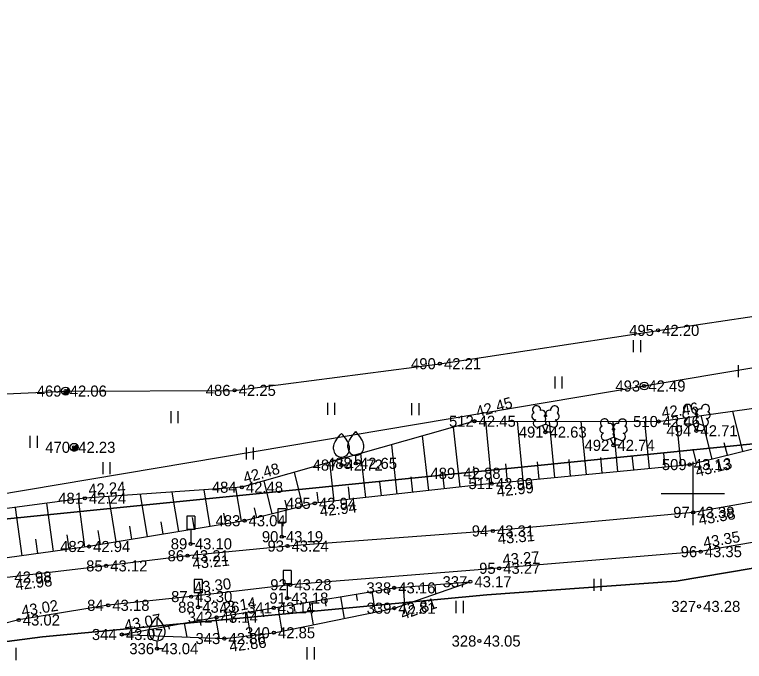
# Model space of a CAD drawing. Extents: x 505800 to 507326, y 6540058 to 6542128.
# Drawn here: x 506157.21 to 506203.25, y 6540239.39 to 6540280.22 of the extents above; entities that cross this region are included whole.
import ezdxf

# ---------------------------------------------------------------- set-up
doc = ezdxf.new("R2010")
doc.units = 0
for name, color, linetype in [('HALJASTUS', 7, 'Continuous'), ('KORGUS-EH2000', 7, 'Continuous'), ('LIIKLUS', 7, 'Continuous'), ('MOOTKORG-EH2000', 7, 'Continuous'), ('MOOTMPUNKT', 7, 'Continuous'), ('MOOTNR', 7, 'Continuous'), ('MOOTPIIR', 7, 'Continuous'), ('MPOHULIIN', 7, 'Continuous'), ('PIIR', 7, 'Continuous'), ('POST', 7, 'Continuous'), ('PUU', 7, 'Continuous'), ('RELJEEF', 7, 'Continuous'), ('TEE', 7, 'Continuous'), ('VORK', 7, 'Continuous')]:
    doc.layers.add(name, color=color, linetype=linetype)

msp = doc.modelspace()

# ---------------------------------------------------------------- linework, layer by layer
at = {"layer": 'HALJASTUS'}
for p, q in [((506196.246, 6540259.68), (506196.246, 6540258.919)), ((506196.701, 6540259.68), (506196.701, 6540258.919)), ((506202.852, 6540258.098), (506202.852, 6540257.337)), ((506191.291, 6540257.377), (506191.291, 6540256.616)), ((506191.746, 6540257.377), (506191.746, 6540256.616)), ((506176.948, 6540255.714), (506176.948, 6540254.953)), ((506177.403, 6540255.714), (506177.403, 6540254.953)), ((506182.253, 6540255.694), (506182.253, 6540254.933)), ((506182.708, 6540255.694), (506182.708, 6540254.933)), ((506167.059, 6540255.194), (506167.059, 6540254.433)), ((506167.514, 6540255.194), (506167.514, 6540254.433)), ((506158.171, 6540253.631), (506158.171, 6540252.87)), ((506158.626, 6540253.631), (506158.626, 6540252.87)), ((506171.813, 6540252.89), (506171.813, 6540252.129)), ((506172.268, 6540252.89), (506172.268, 6540252.129)), ((506162.775, 6540251.979), (506162.775, 6540251.218)), ((506163.23, 6540251.979), (506163.23, 6540251.218)), ((506193.745, 6540244.608), (506193.745, 6540243.847)), ((506194.2, 6540244.608), (506194.2, 6540243.847)), ((506185.057, 6540243.206), (506185.057, 6540242.445)), ((506185.512, 6540243.206), (506185.512, 6540242.445)), ((506157.286, 6540240.242), (506157.286, 6540239.481)), ((506175.648, 6540240.282), (506175.648, 6540239.521)), ((506176.103, 6540240.282), (506176.103, 6540239.521))]:
    msp.add_line(p, q, dxfattribs=at)
at = {"layer": 'KORGUS-EH2000'}
for centre in [(506197.806, 6540260.288), (506184.044, 6540258.184), (506196.936, 6540256.778), (506160.43, 6540256.455), (506171.091, 6540256.503), (506186.229, 6540254.552), (506197.842, 6540254.535), (506190.701, 6540253.865), (506200.224, 6540253.951), (506160.969, 6540252.907), (506194.987, 6540253.033), (506177.835, 6540251.786), (506178.739, 6540251.895), (506199.797, 6540251.818), (506187.313, 6540250.618), (506171.546, 6540250.385), (506161.646, 6540249.691), (506176.15, 6540249.371), (506200.022, 6540248.8), (506171.713, 6540248.272), (506187.383, 6540247.629), (506174.072, 6540247.265), (506161.906, 6540246.646), (506168.324, 6540246.815), (506174.426, 6540246.673), (506168.123, 6540246.063), (506200.494, 6540246.321), (506162.988, 6540245.422), (506187.779, 6540245.271), (506174.602, 6540244.231), (506185.963, 6540244.422), (506181.159, 6540244.035), (506168.346, 6540243.484), (506174.406, 6540243.388), (506163.12, 6540242.933), (506168.79, 6540242.813), (506173.563, 6540242.769), (506181.171, 6540242.752), (506200.392, 6540242.862), (506157.471, 6540242.007), (506169.957, 6540242.178), (506163.976, 6540241.09), (506173.57, 6540241.202), (506170.445, 6540240.835), (506186.532, 6540240.678), (506166.201, 6540240.196)]:
    msp.add_circle(centre, 0.1, dxfattribs=at)
at = {"layer": 'LIIKLUS'}
for p, q in [((506173.822, 6540249.015), (506173.822, 6540248.165)), ((506174.322, 6540249.015), (506173.822, 6540249.015)), ((506174.322, 6540249.015), (506174.322, 6540248.165)), ((506168.074, 6540248.565), (506168.074, 6540247.715)), ((506168.574, 6540248.565), (506168.074, 6540248.565)), ((506168.574, 6540248.565), (506168.574, 6540247.715)), ((506174.322, 6540248.165), (506173.822, 6540248.165)), ((506174.072, 6540248.165), (506174.072, 6540247.265)), ((506168.574, 6540247.715), (506168.074, 6540247.715)), ((506168.324, 6540247.715), (506168.324, 6540246.815)), ((506174.322, 6540247.265), (506174.072, 6540247.265)), ((506168.574, 6540246.815), (506168.324, 6540246.815)), ((506174.156, 6540245.138), (506174.156, 6540244.288)), ((506174.656, 6540245.138), (506174.156, 6540245.138)), ((506174.656, 6540245.138), (506174.656, 6540244.288)), ((506168.54, 6540244.563), (506168.54, 6540243.713)), ((506169.04, 6540244.563), (506168.54, 6540244.563)), ((506169.04, 6540244.563), (506169.04, 6540243.713)), ((506174.656, 6540244.288), (506174.156, 6540244.288)), ((506174.406, 6540244.288), (506174.406, 6540243.388)), ((506169.04, 6540243.713), (506168.54, 6540243.713)), ((506168.79, 6540243.713), (506168.79, 6540242.813)), ((506174.656, 6540243.388), (506174.406, 6540243.388)), ((506169.04, 6540242.813), (506168.79, 6540242.813))]:
    msp.add_line(p, q, dxfattribs=at)
at = {"layer": 'MOOTMPUNKT'}
for centre in [(506197.806, 6540260.288), (506184.044, 6540258.184), (506196.936, 6540256.778), (506160.43, 6540256.455), (506171.091, 6540256.503), (506186.229, 6540254.552), (506197.842, 6540254.535), (506190.701, 6540253.865), (506200.224, 6540253.951), (506160.969, 6540252.907), (506194.987, 6540253.033), (506177.835, 6540251.786), (506178.739, 6540251.895), (506199.797, 6540251.818), (506187.313, 6540250.618), (506171.546, 6540250.385), (506161.646, 6540249.691), (506176.15, 6540249.371), (506200.022, 6540248.8), (506171.713, 6540248.272), (506187.383, 6540247.629), (506174.072, 6540247.265), (506161.906, 6540246.646), (506168.324, 6540246.815), (506174.426, 6540246.673), (506168.123, 6540246.063), (506200.494, 6540246.321), (506162.988, 6540245.422), (506187.779, 6540245.271), (506174.602, 6540244.231), (506185.963, 6540244.422), (506181.159, 6540244.035), (506168.346, 6540243.484), (506174.406, 6540243.388), (506163.12, 6540242.933), (506168.79, 6540242.813), (506173.563, 6540242.769), (506181.171, 6540242.752), (506200.392, 6540242.862), (506157.471, 6540242.007), (506169.957, 6540242.178), (506163.976, 6540241.09), (506173.57, 6540241.202), (506170.445, 6540240.835), (506186.532, 6540240.678), (506166.201, 6540240.196)]:
    msp.add_circle(centre, 0.1, dxfattribs=at)
at = {"layer": 'MOOTPIIR'}
msp.add_lwpolyline([(506083.03, 6540240.114), (506097.119, 6540244.795), (506135.023, 6540255.311), (506160.43, 6540256.455), (506171.091, 6540256.503), (506184.044, 6540258.184), (506197.806, 6540260.288), (506211.896, 6540262.383), (506227.932, 6540267.786), (506240.253, 6540270.959), (506245.955, 6540263.864)], dxfattribs=at)
at = {"layer": 'MPOHULIIN'}
msp.add_lwpolyline([(506112.189, 6540233.927), (506153.828, 6540249.522), (506196.936, 6540256.778), (506240.207, 6540264.027), (506283.784, 6540271.755), (506305.802, 6540315.044)], dxfattribs=at)
at = {"layer": 'PIIR'}
msp.add_lwpolyline([(506133.36, 6540278.52), (506190.15, 6540321.81), (506215.95, 6540254.34), (506141.06, 6540246.81)], close=True, dxfattribs=at)
for points in [[(506272.39, 6540267.75), (506224.13, 6540249.92), (506208.53, 6540246.07), (506198.96, 6540244.45), (506187, 6540243.59), (506158.97, 6540240.95), (506142.88, 6540238.84), (506141.06, 6540246.81), (506215.95, 6540254.34), (506268.55, 6540273.9)], [(506028.99, 6540136.11), (506018.19, 6540200.68), (506049.36, 6540212.6), (506053.99, 6540200.79), (506052.51, 6540200.31), (506055.45, 6540190.69), (506062.61, 6540193.04), (506059.62, 6540202.68), (506057.79, 6540202.01), (506053.1, 6540214.07), (506081.75, 6540225.93), (506090.32, 6540182.64), (506150.17, 6540208.02), (506142.88, 6540238.84), (506158.97, 6540240.95), (506187, 6540243.59), (506198.96, 6540244.45), (506208.53, 6540246.07), (506224.13, 6540249.92), (506272.39, 6540267.75)]]:
    msp.add_lwpolyline(points, dxfattribs=at)
at = {"layer": 'POST'}
for p, q in [((506160.253, 6540256.278), (506160.607, 6540256.631)), ((506160.791, 6540252.73), (506161.145, 6540253.083))]:
    msp.add_line(p, q, dxfattribs=at)
for centre in [(506160.43, 6540256.455), (506196.936, 6540256.778), (506160.969, 6540252.907)]:
    msp.add_circle(centre, 0.25, dxfattribs=at)
for centre, radius, start, end in [((506160.43, 6540256.455), 0.225, 224.8541, 45.0356), ((506160.43, 6540256.455), 0.2, 224.8427, 45.047), ((506160.43, 6540256.455), 0.175, 224.8281, 45.0616), ((506160.43, 6540256.455), 0.15, 224.8087, 45.081), ((506160.43, 6540256.455), 0.125, 224.7814, 45.1083), ((506160.43, 6540256.455), 0.1, 224.7406, 45.1491), ((506160.43, 6540256.455), 0.075, 224.6725, 45.2172), ((506160.43, 6540256.455), 0.05, 224.5363, 45.3534), ((506160.43, 6540256.455), 0.025, 224.1278, 45.7619), ((506160.969, 6540252.907), 0.225, 224.8541, 45.0356), ((506160.969, 6540252.907), 0.2, 224.8427, 45.047), ((506160.969, 6540252.907), 0.175, 224.8281, 45.0616), ((506160.969, 6540252.907), 0.15, 224.8087, 45.081), ((506160.969, 6540252.907), 0.125, 224.7814, 45.1083), ((506160.969, 6540252.907), 0.1, 224.7406, 45.1491), ((506160.969, 6540252.907), 0.075, 224.6725, 45.2172), ((506160.969, 6540252.907), 0.05, 224.5363, 45.3534), ((506160.969, 6540252.907), 0.025, 224.1278, 45.7619)]:
    msp.add_arc(centre, radius, start, end, dxfattribs=at)
at = {"layer": 'PUU'}
for p, q in [((506190.261, 6540254.2), (506190.706, 6540254.375)), ((506190.706, 6540254.375), (506191.146, 6540254.195)), ((506199.784, 6540254.286), (506200.229, 6540254.461)), ((506200.224, 6540253.951), (506200.049, 6540254.391)), ((506200.224, 6540253.951), (506200.404, 6540254.391)), ((506200.229, 6540254.461), (506200.669, 6540254.281)), ((506190.701, 6540253.865), (506190.526, 6540254.305)), ((506190.701, 6540253.865), (506190.881, 6540254.305)), ((506191.081, 6540253.865), (506190.701, 6540253.865)), ((506200.604, 6540253.951), (506200.224, 6540253.951)), ((506194.547, 6540253.368), (506194.992, 6540253.543)), ((506194.987, 6540253.033), (506194.812, 6540253.473)), ((506194.987, 6540253.033), (506195.167, 6540253.473)), ((506194.992, 6540253.543), (506195.432, 6540253.363)), ((506195.367, 6540253.033), (506194.987, 6540253.033)), ((506177.835, 6540251.786), (506177.835, 6540252.286)), ((506178.739, 6540251.895), (506178.739, 6540252.395)), ((506178.235, 6540251.786), (506177.835, 6540251.786)), ((506179.139, 6540251.895), (506178.739, 6540251.895)), ((506166.201, 6540240.196), (506166.201, 6540240.696)), ((506166.601, 6540240.196), (506166.201, 6540240.196))]:
    msp.add_line(p, q, dxfattribs=at)
for points in [[(506190.706, 6540254.87), (506190.686, 6540254.795), (506190.686, 6540254.775), (506190.696, 6540254.745), (506190.716, 6540254.71), (506190.721, 6540254.69), (506190.706, 6540254.655), (506190.681, 6540254.605), (506190.676, 6540254.58), (506190.681, 6540254.565), (506190.691, 6540254.535), (506190.726, 6540254.475), (506190.731, 6540254.455), (506190.726, 6540254.435), (506190.711, 6540254.4), (506190.706, 6540254.375)], [(506200.229, 6540254.956), (506200.209, 6540254.881), (506200.209, 6540254.861), (506200.219, 6540254.831), (506200.239, 6540254.796), (506200.244, 6540254.776), (506200.229, 6540254.741), (506200.204, 6540254.691), (506200.199, 6540254.666), (506200.204, 6540254.651), (506200.214, 6540254.621), (506200.249, 6540254.561), (506200.254, 6540254.541), (506200.249, 6540254.521), (506200.234, 6540254.486), (506200.229, 6540254.461)], [(506178.239, 6540252.895), (506178.239, 6540253.045), (506178.249, 6540253.11), (506178.284, 6540253.24), (506178.344, 6540253.36), (506178.489, 6540253.595), (506178.649, 6540253.8), (506178.739, 6540253.895)], [(506179.239, 6540252.895), (506179.239, 6540253.045), (506179.229, 6540253.11), (506179.194, 6540253.24), (506179.134, 6540253.36), (506178.989, 6540253.595), (506178.829, 6540253.8), (506178.739, 6540253.895)], [(506194.992, 6540254.038), (506194.972, 6540253.963), (506194.972, 6540253.943), (506194.982, 6540253.913), (506195.002, 6540253.878), (506195.007, 6540253.858), (506194.992, 6540253.823), (506194.967, 6540253.773), (506194.962, 6540253.748), (506194.967, 6540253.733), (506194.977, 6540253.703), (506195.012, 6540253.643), (506195.017, 6540253.623), (506195.012, 6540253.603), (506194.997, 6540253.568), (506194.992, 6540253.543)], [(506177.335, 6540252.786), (506177.335, 6540252.936), (506177.345, 6540253.001), (506177.38, 6540253.131), (506177.44, 6540253.251), (506177.585, 6540253.486), (506177.745, 6540253.691), (506177.835, 6540253.786)], [(506178.335, 6540252.786), (506178.335, 6540252.936), (506178.325, 6540253.001), (506178.29, 6540253.131), (506178.23, 6540253.251), (506178.085, 6540253.486), (506177.925, 6540253.691), (506177.835, 6540253.786)], [(506165.701, 6540241.196), (506165.701, 6540241.346), (506165.711, 6540241.411), (506165.746, 6540241.541), (506165.806, 6540241.661), (506165.951, 6540241.896), (506166.111, 6540242.101), (506166.201, 6540242.196)], [(506166.701, 6540241.196), (506166.701, 6540241.346), (506166.691, 6540241.411), (506166.656, 6540241.541), (506166.596, 6540241.661), (506166.451, 6540241.896), (506166.291, 6540242.101), (506166.201, 6540242.196)]]:
    msp.add_lwpolyline(points, dxfattribs=at)
for centre, radius, start, end in [((506190.144, 6540255.279), 0.256, 111.5027, 232.5173), ((506190.144, 6540255.279), 0.256, 350.4856, 111.5002), ((506190.479, 6540255.028), 0.224, 308.5041, 111.5725), ((506190.942, 6540255.024), 0.225, 67.7016, 230.5126), ((506191.28, 6540255.27), 0.256, 67.6168, 188.6314), ((506191.28, 6540255.27), 0.256, 306.5997, 67.6143), ((506199.667, 6540255.365), 0.256, 111.5027, 232.5173), ((506199.667, 6540255.365), 0.256, 350.4856, 111.5002), ((506200.001, 6540255.114), 0.224, 308.5041, 111.5725), ((506200.464, 6540255.11), 0.225, 67.7016, 230.5126), ((506200.803, 6540255.356), 0.256, 67.6168, 188.6314), ((506200.803, 6540255.356), 0.256, 306.5997, 67.6143), ((506190.07, 6540254.868), 0.224, 111.4304, 274.4987), ((506190.705, 6540254.632), 0.237, 66.7655, 111.5015), ((506191.348, 6540254.858), 0.224, 264.6183, 67.6866), ((506199.593, 6540254.953), 0.224, 111.4304, 274.4987), ((506200.228, 6540254.718), 0.237, 66.7655, 111.5015), ((506200.87, 6540254.943), 0.224, 264.6183, 67.6866), ((506190.175, 6540254.423), 0.237, 111.5014, 291.5004), ((506191.236, 6540254.415), 0.237, 247.6166, 67.6155), ((506194.429, 6540254.447), 0.256, 111.5027, 232.5173), ((506194.429, 6540254.447), 0.256, 350.4856, 111.5002), ((506194.764, 6540254.196), 0.224, 308.5041, 111.5725), ((506195.227, 6540254.192), 0.225, 67.7016, 230.5126), ((506195.565, 6540254.438), 0.256, 67.6168, 188.6314), ((506195.565, 6540254.438), 0.256, 306.5997, 67.6143), ((506199.697, 6540254.509), 0.237, 111.5014, 291.5004), ((506200.759, 6540254.501), 0.237, 247.6166, 67.6155), ((506194.356, 6540254.035), 0.224, 111.4304, 274.4987), ((506194.991, 6540253.8), 0.237, 66.7655, 111.5015), ((506195.633, 6540254.026), 0.224, 264.6183, 67.6866), ((506194.46, 6540253.591), 0.237, 111.5014, 291.5004), ((506195.521, 6540253.583), 0.237, 247.6166, 67.6155), ((506177.835, 6540252.786), 0.5, 180, 0), ((506178.739, 6540252.895), 0.5, 180, 0), ((506166.201, 6540241.196), 0.5, 180, 0)]:
    msp.add_arc(centre, radius, start, end, dxfattribs=at)
at = {"layer": 'RELJEEF'}
for p, q in [((506201.212, 6540252.168), (506200.534, 6540254.91)), ((506203.154, 6540252.649), (506202.526, 6540255.187)), ((506187.313, 6540250.618), (506186.935, 6540254.551)), ((506189.303, 6540250.809), (506188.944, 6540254.548)), ((506191.294, 6540251.001), (506190.954, 6540254.545)), ((506193.285, 6540251.192), (506192.963, 6540254.542)), ((506195.276, 6540251.383), (506194.973, 6540254.539)), ((506197.267, 6540251.575), (506196.982, 6540254.536)), ((506199.258, 6540251.766), (506198.976, 6540254.693)), ((506185.325, 6540250.396), (506184.903, 6540254.175)), ((506183.337, 6540250.174), (506182.952, 6540253.622)), ((506181.35, 6540249.952), (506181.002, 6540253.068)), ((506202.183, 6540252.408), (506201.987, 6540253.2)), ((506179.362, 6540249.73), (506179.051, 6540252.515)), ((506198.262, 6540251.671), (506198.179, 6540252.536)), ((506200.242, 6540251.928), (506200.031, 6540252.781)), ((506192.29, 6540251.096), (506192.19, 6540252.13)), ((506194.28, 6540251.288), (506194.187, 6540252.264)), ((506196.271, 6540251.479), (506196.183, 6540252.397)), ((506177.374, 6540249.508), (506177.1, 6540251.961)), ((506186.319, 6540250.507), (506186.187, 6540251.69)), ((506188.308, 6540250.714), (506188.197, 6540251.864)), ((506190.299, 6540250.905), (506190.194, 6540251.997)), ((506175.405, 6540249.186), (506174.874, 6540251.33)), ((506184.331, 6540250.285), (506184.21, 6540251.369)), ((506173.463, 6540248.706), (506172.949, 6540250.783)), ((506180.356, 6540249.841), (506180.257, 6540250.726)), ((506182.344, 6540250.063), (506182.234, 6540251.048)), ((506169.546, 6540247.913), (506169.163, 6540250.218)), ((506171.519, 6540248.24), (506171.167, 6540250.359)), ((506178.368, 6540249.619), (506178.28, 6540250.405)), ((506163.626, 6540246.932), (506163.151, 6540249.796)), ((506165.599, 6540247.259), (506165.155, 6540249.937)), ((506167.573, 6540247.586), (506167.159, 6540250.078)), ((506176.381, 6540249.397), (506176.304, 6540250.083)), ((506159.671, 6540246.338), (506159.253, 6540249.374)), ((506161.652, 6540246.611), (506161.236, 6540249.637)), ((506174.434, 6540248.946), (506174.277, 6540249.579)), ((506157.69, 6540246.066), (506157.27, 6540249.112)), ((506172.492, 6540248.465), (506172.341, 6540249.079)), ((506168.559, 6540247.749), (506168.44, 6540248.469)), ((506170.532, 6540248.077), (506170.422, 6540248.74)), ((506164.613, 6540247.095), (506164.475, 6540247.927)), ((506166.586, 6540247.422), (506166.457, 6540248.198)), ((506162.64, 6540246.768), (506162.493, 6540247.655)), ((506158.68, 6540246.202), (506158.555, 6540247.114)), ((506160.662, 6540246.475), (506160.536, 6540247.384)), ((506183.717, 6540244.241), (506183.764, 6540243.656)), ((506184.714, 6540244.322), (506184.722, 6540244.224)), ((506185.711, 6540244.402), (506185.716, 6540244.336)), ((506179.745, 6540243.799), (506179.961, 6540242.505)), ((506180.731, 6540243.964), (506180.794, 6540243.586)), ((506181.724, 6540244.08), (506181.813, 6540242.976)), ((506182.72, 6540244.161), (506182.741, 6540243.907)), ((506176.786, 6540243.306), (506176.856, 6540242.886)), ((506177.772, 6540243.471), (506178, 6540242.105)), ((506178.759, 6540243.635), (506178.825, 6540243.236)), ((506173.827, 6540242.813), (506174.078, 6540241.306)), ((506174.813, 6540242.977), (506174.887, 6540242.536)), ((506175.799, 6540243.142), (506176.039, 6540241.706)), ((506171.853, 6540242.489), (506172.092, 6540241.029)), ((506172.84, 6540242.651), (506172.914, 6540242.199)), ((506168.896, 6540241.985), (506168.956, 6540241.656)), ((506169.88, 6540242.164), (506170.119, 6540240.848)), ((506170.866, 6540242.327), (506170.936, 6540241.903)), ((506165.944, 6540241.448), (506166.024, 6540241.01)), ((506166.928, 6540241.627), (506166.964, 6540241.43)), ((506167.912, 6540241.806), (506168.071, 6540240.929)), ((506163.976, 6540241.09), (506163.976, 6540241.09)), ((506164.96, 6540241.269), (506164.972, 6540241.204))]:
    msp.add_line(p, q, dxfattribs=at)
for points in [[(506186.229, 6540254.552), (506197.842, 6540254.535), (506207.175, 6540255.835), (506212.996, 6540256.696), (506222.499, 6540257.905), (506235.612, 6540261.879), (506240.802, 6540263.724)], [(506187.313, 6540250.618), (506199.797, 6540251.818), (506207.632, 6540253.756), (506214.067, 6540252.925), (506223.339, 6540254.808), (506236.54, 6540259.529), (506241.741, 6540261.71)], [(506186.229, 6540254.552), (506171.546, 6540250.385), (506161.646, 6540249.691), (506149.749, 6540248.117), (506144.177, 6540245.106)], [(506187.313, 6540250.618), (506176.15, 6540249.371), (506171.713, 6540248.272), (506161.906, 6540246.646), (506150.046, 6540245.013), (506144.177, 6540245.106)], [(506163.976, 6540241.09), (506169.957, 6540242.178), (506173.563, 6540242.769), (506181.159, 6540244.035), (506185.963, 6540244.422)], [(506163.976, 6540241.09), (506170.445, 6540240.835), (506173.57, 6540241.202), (506181.171, 6540242.752), (506185.963, 6540244.422)]]:
    msp.add_lwpolyline(points, dxfattribs=at)
at = {"layer": 'TEE'}
for points in [[(506250.031, 6540264.042), (506237.432, 6540259.066), (506223.872, 6540254.219), (506212.634, 6540251.013), (506200.022, 6540248.8), (506187.383, 6540247.629), (506174.426, 6540246.673), (506168.123, 6540246.063), (506162.988, 6540245.422), (506156.937, 6540244.719), (506147.401, 6540244.066), (506139.254, 6540244.367), (506135.743, 6540244.402), (506126.133, 6540243.916), (506116.327, 6540241.664), (506104.313, 6540238.326), (506099.073, 6540236.742), (506091.024, 6540234.378), (506084.768, 6540232.16)], [(506250.904, 6540261.782), (506238.366, 6540256.809), (506224.827, 6540251.952), (506213.198, 6540248.536), (506200.494, 6540246.321), (506187.779, 6540245.271), (506174.602, 6540244.231), (506168.346, 6540243.484), (506163.12, 6540242.933), (506157.471, 6540242.007), (506148.214, 6540239.664), (506142.677, 6540239.46), (506137.814, 6540240.039)]]:
    msp.add_lwpolyline(points, dxfattribs=at)
at = {"layer": 'VORK'}
for p, q in [((506200, 6540252), (506200, 6540248)), ((506198, 6540250), (506202, 6540250))]:
    msp.add_line(p, q, dxfattribs=at)

# ---------------------------------------------------------------- texts
at = {"layer": 'KORGUS-EH2000'}
for s, p in [(' 42.20', (506197.806, 6540259.938)), (' 42.21', (506184.044, 6540257.834)), (' 42.25', (506171.091, 6540256.153)), (' 43.28', (506200.392, 6540242.512)), (' 43.05', (506186.532, 6540240.328))]:
    msp.add_text(s, height=0.7, dxfattribs=at).set_placement(p)
for s, rotation, p in [(' 42.45', 15.8417, (506186.181, 6540254.72)), (' 42.46', 7.9302, (506197.818, 6540254.708)), (' 43.13', 13.8968, (506200.008, 6540250.969)), (' 42.48', 15.8417, (506171.498, 6540250.554)), (' 42.24', 4.0122, (506161.634, 6540249.865)), (' 42.99', 6.3739, (506187.41, 6540249.748)), (' 42.94', 6.3739, (506176.247, 6540248.502)), (' 43.38', 9.9539, (506200.173, 6540247.938)), (' 43.31', 5.2914, (506187.464, 6540246.758)), (' 43.35', 9.8905, (506200.464, 6540246.493)), (' 43.21', 5.5291, (506168.207, 6540245.192)), (' 43.27', 4.7203, (506187.765, 6540245.445)), (' 42.98', 6.6344, (506157.038, 6540243.849)), (' 43.30', 6.8071, (506168.325, 6540243.658)), (' 43.02', 9.3101, (506157.443, 6540242.179)), (' 43.14', 9.3028, (506169.928, 6540242.351)), (' 42.81', 19.2115, (506181.459, 6540241.926)), (' 43.07', 10.3103, (506163.945, 6540241.263)), (' 42.86', 6.6943, (506170.547, 6540239.966))]:
    msp.add_text(s, height=0.7, rotation=rotation, dxfattribs=at).set_placement(p)
at = {"layer": 'MOOTKORG-EH2000'}
for s, p in [(' 42.20', (506197.806, 6540259.938)), (' 42.21', (506184.044, 6540257.834)), (' 42.49', (506196.936, 6540256.428)), (' 42.06', (506160.43, 6540256.105)), (' 42.25', (506171.091, 6540256.153)), (' 42.45', (506186.229, 6540254.202)), (' 42.46', (506197.842, 6540254.185)), (' 42.71', (506200.224, 6540253.601)), (' 42.63', (506190.701, 6540253.515)), (' 42.74', (506194.987, 6540252.683)), (' 42.23', (506160.969, 6540252.557)), (' 42.72', (506177.835, 6540251.436)), (' 42.65', (506178.739, 6540251.545)), (' 43.13', (506199.797, 6540251.468)), (' 42.88', (506185.268, 6540250.914)), (' 42.48', (506171.546, 6540250.035)), (' 42.99', (506187.313, 6540250.268)), (' 42.24', (506161.646, 6540249.341)), (' 42.94', (506176.15, 6540249.021)), (' 43.38', (506200.022, 6540248.45)), (' 43.04', (506171.713, 6540247.923)), (' 43.31', (506187.383, 6540247.279)), (' 43.19', (506174.072, 6540246.915)), (' 42.94', (506161.906, 6540246.296)), (' 43.10', (506168.324, 6540246.465)), (' 43.24', (506174.426, 6540246.323)), (' 43.35', (506200.494, 6540245.971)), (' 43.21', (506168.123, 6540245.713)), (' 43.12', (506162.988, 6540245.072)), (' 43.27', (506187.779, 6540244.921)), (' 42.98', (506156.937, 6540244.369)), (' 43.17', (506185.963, 6540244.072)), (' 43.28', (506174.602, 6540243.881)), (' 43.16', (506181.159, 6540243.685)), (' 43.30', (506168.346, 6540243.134)), (' 43.18', (506174.406, 6540243.038)), (' 43.18', (506163.12, 6540242.583)), (' 43.26', (506168.79, 6540242.463)), (' 43.14', (506173.563, 6540242.419)), (' 42.81', (506181.171, 6540242.402)), (' 43.28', (506200.392, 6540242.512)), (' 43.02', (506157.471, 6540241.656)), (' 43.14', (506169.957, 6540241.828)), (' 43.07', (506163.976, 6540240.74)), (' 42.85', (506173.57, 6540240.852)), (' 42.86', (506170.445, 6540240.485)), (' 43.05', (506186.532, 6540240.328)), (' 43.04', (506166.201, 6540239.846))]:
    msp.add_text(s, height=0.7, dxfattribs=at).set_placement(p)
at = {"layer": 'MOOTNR'}
for s, p in [('495 ', (506195.986, 6540259.938)), ('490 ', (506182.224, 6540257.834)), ('493 ', (506195.116, 6540256.428)), ('469 ', (506158.61, 6540256.105)), ('486 ', (506169.271, 6540256.153)), ('512 ', (506184.619, 6540254.202)), ('510 ', (506196.232, 6540254.185)), ('494 ', (506198.334, 6540253.601)), ('491 ', (506189.021, 6540253.515)), ('492 ', (506193.167, 6540252.683)), ('470 ', (506159.149, 6540252.557)), ('487 ', (506176.015, 6540251.436)), ('488 ', (506176.919, 6540251.545)), ('509 ', (506198.048, 6540251.468)), ('489 ', (506183.448, 6540250.914)), ('484 ', (506169.656, 6540250.035)), ('511 ', (506185.843, 6540250.268)), ('481 ', (506159.966, 6540249.341)), ('485 ', (506174.33, 6540249.021)), ('97 ', (506198.762, 6540248.45)), ('483 ', (506169.893, 6540247.923)), ('94 ', (506186.053, 6540247.279)), ('90 ', (506172.812, 6540246.915)), ('482 ', (506160.087, 6540246.296)), ('89 ', (506167.064, 6540246.465)), ('93 ', (506173.166, 6540246.323)), ('96 ', (506199.234, 6540245.971)), ('86 ', (506166.863, 6540245.713)), ('85 ', (506161.728, 6540245.072)), ('95 ', (506186.519, 6540244.921)), ('337 ', (506184.213, 6540244.072)), ('92 ', (506173.342, 6540243.881)), ('338 ', (506179.409, 6540243.685)), ('87 ', (506167.086, 6540243.134)), ('91 ', (506173.286, 6540243.038)), ('84 ', (506161.79, 6540242.583)), ('88 ', (506167.53, 6540242.463)), ('341 ', (506171.883, 6540242.419)), ('339 ', (506179.421, 6540242.402)), ('327 ', (506198.642, 6540242.512)), ('342 ', (506168.137, 6540241.828)), ('344 ', (506162.087, 6540240.74)), ('340 ', (506171.75, 6540240.852)), ('343 ', (506168.625, 6540240.485)), ('328 ', (506184.782, 6540240.328)), ('336 ', (506164.451, 6540239.846))]:
    msp.add_text(s, height=0.7, dxfattribs=at).set_placement(p)

doc.saveas('drawing.dxf')
